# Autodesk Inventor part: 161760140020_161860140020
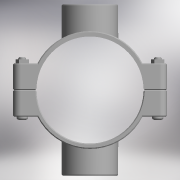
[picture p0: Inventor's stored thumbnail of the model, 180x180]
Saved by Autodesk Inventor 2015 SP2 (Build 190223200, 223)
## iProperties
Created: 2017-05
Part Number: 161760140020_161860140020
Material: Generic
Description: PLASSON DOUBLE SADDLE 140-2"
Document SubType Name: Modeling
Designer: KIM
Density: 1 g/cm^3
Appearance: Default
Author: KIM
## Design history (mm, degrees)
derived "16176.ipt"
feature "Solid1::16176.ipt"
feature "Solid2::16176.ipt"
tag "TaggingFeature1"
body "Solid1"
body "Solid2"
other parameters: "d0" = 154, "d1" = 201, "d4" = 136, "d5" = 0, "d6" = 10.05, "d7" = 201, "d8" = 0.1, "d10" = 0, "d11" = 1.4, "d20" = 1.4, "d23" = 1.4, "d36" = 15, "d37" = 12, "d38" = 78, "d39" = 0, "d40" = 3, "d41" = 5, "d42" = 0, "d44" = 3, "d45" = 0, "d46" = 1.4, "d52" = 56.656, "d54" = 0, "d57" = 0, "d58" = 151.2, "d60" = 0, "d62" = 15, "d63" = 12, "d66" = 112, "d67" = 224, "d68" = 73.6528, "d69" = 56.656, "d71" = 0, "d74" = 0, "d75" = 1.4, "G_" = 56.656, "A_" = 112, "L_" = 201, "L_1" = 136
